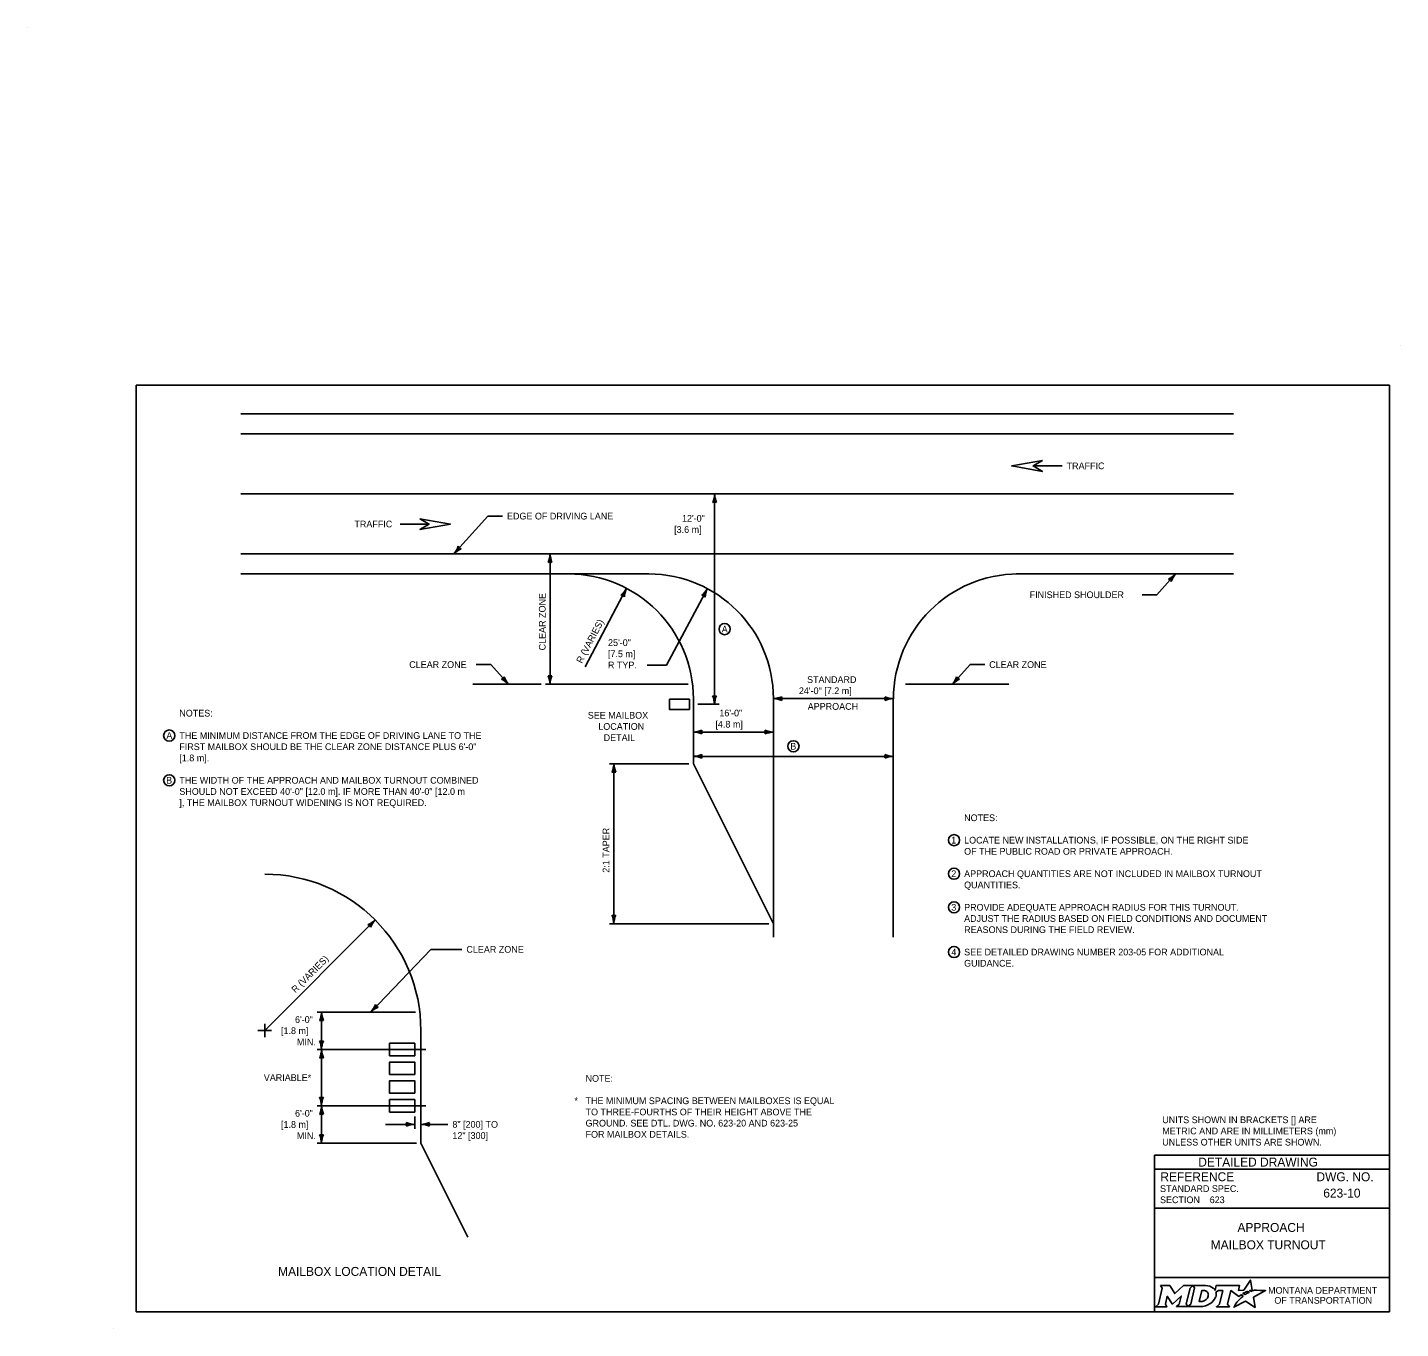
# Model space of a CAD drawing. Extents: x 49991.4 to 50021, y 49987.6 to 50011.4.
# Drawn here: x 50008.76 to 50021.04, y 49999.74 to 50011.36 of the extents above; entities that cross this region are included whole.
import ezdxf

# ---------------------------------------------------------------- set-up
doc = ezdxf.new("R2010")
doc.units = 0
for name, color, linetype in [('Default', 7, 'Continuous'), ('Level 1', 7, 'Continuous'), ('Level 2', 7, 'Continuous'), ('Level 3', 7, 'Continuous'), ('Level 4', 7, 'Continuous'), ('Level 5', 7, 'Continuous')]:
    doc.layers.add(name, color=color, linetype=linetype)

# ---------------------------------------------------------------- blocks, each defined once
blk = doc.blocks.new('ARR')
at = {"layer": 'Level 3'}
for centre, radius, start, end in [((1.5, 37), 37.1, 247.456, 267.6395), ((-21.4, 0), 9.13, 342.1388, 17.8612), ((1.9, -38.8), 38.8, 92.8273, 112.0772)]:
    blk.add_arc(centre, radius, start, end, dxfattribs=at)

msp = doc.modelspace()

# ---------------------------------------------------------------- linework, layer by layer
at = {"layer": 'Default'}
for points in [[(50018.893, 50000.121), (50018.907, 50000.097), (50018.874, 49999.954), (50018.848, 49999.931), (50018.95, 49999.931), (50018.936, 49999.954), (50018.952, 50000.024), (50018.996, 49999.955), (50019.002, 49999.955), (50019.077, 50000.025), (50019.06, 49999.954), (50019.035, 49999.932), (50019.137, 49999.932), (50019.123, 49999.955), (50019.156, 50000.097)], [(50019.156, 50000.097), (50019.182, 50000.121), (50019.099, 50000.121), (50019.02, 50000.048), (50018.975, 50000.12), (50018.893, 50000.121)], [(50019.295, 50000.121), (50019.182, 50000.121), (50019.196, 50000.098), (50019.163, 49999.954), (50019.137, 49999.932), (50019.248, 49999.932)], [(50019.7, 50000.068), (50019.69, 50000.074), (50019.702, 50000.076), (50019.713, 50000.078), (50019.696, 50000.168), (50019.636, 50000.077), (50019.589, 50000.076), (50019.599, 50000.12), (50019.39, 50000.121), (50019.38, 50000.078), (50019.374, 50000.086)], [(50019.319, 50000.034), (50019.318, 50000.026), (50019.315, 50000.017), (50019.311, 50000.008), (50019.305, 50000.001), (50019.299, 49999.994), (50019.291, 49999.988), (50019.282, 49999.983), (50019.273, 49999.979), (50019.264, 49999.977), (50019.255, 49999.976), (50019.239, 49999.976), (50019.263, 50000.076), (50019.279, 50000.076), (50019.286, 50000.075), (50019.294, 50000.073), (50019.301, 50000.07), (50019.307, 50000.066), (50019.311, 50000.061), (50019.315, 50000.055), (50019.318, 50000.049), (50019.319, 50000.042), (50019.32, 50000.038), (50019.319, 50000.034)], [(50019.387, 50000.062), (50019.411, 50000.075), (50019.448, 50000.075), (50019.42, 49999.954), (50019.392, 49999.931), (50019.508, 49999.931), (50019.491, 49999.954), (50019.52, 50000.075), (50019.591, 50000.023), (50019.612, 50000.038), (50019.632, 50000.027)], [(50019.576, 49999.971), (50019.561, 49999.947), (50019.556, 49999.939), (50019.55, 49999.931), (50019.548, 49999.926), (50019.653, 49999.979), (50019.737, 49999.924), (50019.724, 50000.017), (50019.831, 50000.075), (50019.782, 50000.076), (50019.751, 50000.077), (50019.731, 50000.077), (50019.724, 50000.075), (50019.719, 50000.074), (50019.711, 50000.072), (50019.7, 50000.068)], [(50019.59, 49999.987), (50019.59, 49999.987)], [(50019.65, 50000.04), (50019.648, 50000.039), (50019.629, 50000.048), (50019.639, 50000.054), (50019.644, 50000.056), (50019.652, 50000.06), (50019.658, 50000.063), (50019.666, 50000.066), (50019.673, 50000.068), (50019.685, 50000.061), (50019.681, 50000.059), (50019.676, 50000.056), (50019.672, 50000.054), (50019.667, 50000.051), (50019.665, 50000.05), (50019.662, 50000.049), (50019.66, 50000.047), (50019.658, 50000.046), (50019.655, 50000.044), (50019.652, 50000.042), (50019.65, 50000.04)], [(50019.293, 49999.939), (50019.302, 49999.942), (50019.315, 49999.947), (50019.335, 49999.958)]]:
    msp.add_lwpolyline(points, dxfattribs=at)
for centre, radius, start, end in [((50019.274, 50000.059), 0.118, 300.9103, 339.1383), ((50019.319, 50000.042), 0.0709, 339.5329, 15.8582)]:
    msp.add_arc(centre, radius, start, end, dxfattribs=at)
for centre, major_axis, ratio, start_param, end_param in [((50019.293, 50000.073), (0.0834, -0.0037), 0.568097, 0.61298, 1.570796), ((50019.349, 50000.081), (0.0361, -0.0295), 0.469099, 1.225588, 1.570796), ((50019.583, 49999.979), (-0.00694, -0.00806), 0.008222, 0, 3.137361), ((50019.6, 49999.997), (-0.0098, -0.0102), 0.016458, 3.141593, 6.279097), ((50019.621, 50000.017), (-0.0112, -0.0097), 0.021651, 3.157348, 6.283185), ((50019.248, 50000.08), (0, 0.148), 0.987302, 3.139398, 3.456847)]:
    msp.add_ellipse(centre, major_axis=major_axis, ratio=ratio, start_param=start_param, end_param=end_param, dxfattribs=at)
at = {"layer": 'Level 1'}
for p, q in [((50008.765, 50011.363), (50008.765, 50011.363)), ((50021.038, 50008.524), (50021.038, 50008.524)), ((50010.671, 50007.909), (50019.545, 50007.909)), ((50010.671, 50007.73), (50019.545, 50007.73)), ((50010.671, 50006.658), (50019.545, 50006.658)), ((50013.6, 50006.479), (50010.671, 50006.479)), ((50014.318, 50006.479), (50013.6, 50006.479)), ((50017.602, 50006.479), (50019.545, 50006.479)), ((50012.745, 50005.493), (50013.356, 50005.493)), ((50016.612, 50005.493), (50017.537, 50005.493)), ((50014.717, 50005.362), (50014.717, 50004.783)), ((50015.432, 50005.365), (50015.432, 50004.661)), ((50016.504, 50005.362), (50016.504, 50003.232)), ((50014.717, 50004.783), (50015.432, 50003.353)), ((50015.432, 50004.661), (50015.432, 50003.232)), ((50012.282, 50002.4), (50012.282, 50001.391)), ((50012.282, 50001.391), (50012.701, 50000.553)), ((50009.537, 49999.736), (50009.537, 49999.736))]:
    msp.add_line(p, q, dxfattribs=at)
for points in [[(50020.938, 50008.165), (50009.737, 50008.165), (50009.737, 49999.886), (50020.938, 49999.886)], [(50014.503, 50005.359), (50014.503, 50005.269), (50014.681, 50005.269), (50014.681, 50005.359)], [(50012.226, 50002.173), (50012.226, 50002.285), (50012.002, 50002.285), (50012.002, 50002.173)], [(50012.226, 50002.006), (50012.226, 50002.117), (50012.002, 50002.117), (50012.002, 50002.006)], [(50012.226, 50001.838), (50012.226, 50001.95), (50012.002, 50001.95), (50012.002, 50001.838)], [(50012.226, 50001.67), (50012.226, 50001.782), (50012.002, 50001.782), (50012.002, 50001.67)]]:
    msp.add_lwpolyline(points, close=True, dxfattribs=at)
for centre, radius, start, end in [((50013.6, 50005.362), 1.117, 0, 90), ((50014.318, 50005.365), 1.114, 360, 90), ((50017.622, 50005.362), 1.117, 90, 180), ((50010.885, 50002.4), 1.396, 0, 90)]:
    msp.add_arc(centre, radius, start, end, dxfattribs=at)
at = {"layer": 'Level 2'}
for centre in [(50014.996, 50005.986), (50010.032, 50005.035), (50015.611, 50004.939), (50010.032, 50004.635), (50017.047, 50004.1), (50017.047, 50003.8), (50017.047, 50003.5), (50017.047, 50003.1)]:
    msp.add_circle(centre, 0.05, dxfattribs=at)
at = {"layer": 'Level 3'}
for p, q in [((50018.013, 50007.445), (50017.753, 50007.445)), ((50014.906, 50006.658), (50014.906, 50007.194)), ((50012.577, 50006.658), (50012.88, 50006.996)), ((50012.88, 50006.996), (50013.011, 50006.996)), ((50012.095, 50006.925), (50012.355, 50006.925)), ((50013.436, 50006.658), (50013.436, 50005.493)), ((50014.906, 50005.314), (50014.906, 50006.658)), ((50018.858, 50006.293), (50019.026, 50006.479)), ((50013.751, 50005.649), (50014.12, 50006.351)), ((50014.478, 50005.665), (50014.843, 50006.348)), ((50018.727, 50006.293), (50018.858, 50006.293)), ((50012.775, 50005.669), (50012.907, 50005.669)), ((50012.907, 50005.669), (50013.065, 50005.493)), ((50014.303, 50005.665), (50014.478, 50005.665)), ((50017.19, 50005.669), (50017.032, 50005.493)), ((50017.321, 50005.669), (50017.19, 50005.669)), ((50014.669, 50005.493), (50013.396, 50005.493)), ((50014.757, 50005.314), (50014.946, 50005.314)), ((50015.432, 50005.365), (50016.504, 50005.365)), ((50014.717, 50005.066), (50015.432, 50005.066)), ((50014.677, 50004.783), (50013.966, 50004.783)), ((50014.006, 50004.783), (50014.006, 50003.353)), ((50014.717, 50004.849), (50016.504, 50004.849)), ((50010.885, 50002.4), (50011.873, 50003.387)), ((50015.392, 50003.353), (50013.966, 50003.353)), ((50012.369, 50003.124), (50011.834, 50002.564)), ((50012.648, 50003.124), (50012.369, 50003.124)), ((50012.232, 50002.564), (50011.353, 50002.564)), ((50011.393, 50002.229), (50011.393, 50002.564)), ((50010.885, 50002.46), (50010.885, 50002.4)), ((50010.885, 50002.4), (50010.825, 50002.4)), ((50010.885, 50002.4), (50010.885, 50002.34)), ((50010.945, 50002.4), (50010.885, 50002.4)), ((50011.393, 50002.229), (50011.393, 50001.726)), ((50011.393, 50001.726), (50011.393, 50001.391)), ((50012.226, 50001.63), (50012.226, 50001.52)), ((50012.226, 50001.56), (50011.964, 50001.56)), ((50012.523, 50001.56), (50012.282, 50001.56)), ((50012.242, 50001.391), (50011.353, 50001.391))]:
    msp.add_line(p, q, dxfattribs=at)
for points in [[(50017.836, 50007.493), (50017.563, 50007.445), (50017.836, 50007.396), (50017.753, 50007.445)], [(50012.272, 50006.973), (50012.545, 50006.925), (50012.272, 50006.877), (50012.355, 50006.925)]]:
    msp.add_lwpolyline(points, close=True, dxfattribs=at)
at = {"layer": 'Level 4'}
for p, q in [((50020.938, 50001.286), (50018.838, 50001.286)), ((50018.838, 50001.286), (50018.838, 49999.886)), ((50020.938, 50001.161), (50018.838, 50001.161)), ((50019.332, 50000.886), (50019.332, 50000.886)), ((50020.574, 50000.946), (50020.574, 50000.946)), ((50020.938, 50000.811), (50018.838, 50000.811)), ((50019.888, 50000.562), (50019.888, 50000.562)), ((50020.938, 50000.193), (50018.838, 50000.193))]:
    msp.add_line(p, q, dxfattribs=at)
at = {"layer": 'Level 5'}
for p, q in [((50010.671, 50007.194), (50019.545, 50007.194)), ((50012.326, 50002.229), (50011.353, 50002.229)), ((50012.326, 50001.726), (50011.353, 50001.726))]:
    msp.add_line(p, q, dxfattribs=at)

# ---------------------------------------------------------------- block references
at = {"layer": 'Level 3'}
for p, xscale, yscale, rotation in [((50014.906, 50007.194), 0.006, 0.006, 90), ((50012.577, 50006.658), 0.006000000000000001, 0.006, -131.9157369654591), ((50013.436, 50006.658), 0.006, 0.006, 90), ((50019.026, 50006.479), 0.006, 0.006000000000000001, 48.08426303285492), ((50014.12, 50006.351), 0.006000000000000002, 0.006, 62.28598908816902), ((50014.843, 50006.348), 0.006, 0.005999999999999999, 61.86112302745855), ((50013.065, 50005.493), 0.006, 0.006, -48.08426303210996), ((50013.436, 50005.493), 0.006, 0.006, -90), ((50017.032, 50005.493), 0.006, 0.006, -131.91573697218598), ((50014.906, 50005.314), 0.006, 0.006, -90), ((50015.432, 50005.365), 0.006, 0.006, 180), ((50014.717, 50005.066), 0.006, 0.006, 180), ((50014.006, 50004.783), 0.006, 0.006, 90), ((50014.717, 50004.849), 0.006, 0.006, 180), ((50014.006, 50003.353), 0.006, 0.006, -90), ((50011.873, 50003.387), 0.005999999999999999, 0.006, 44.99999999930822), ((50011.393, 50002.564), 0.006, 0.006, 90), ((50011.834, 50002.564), 0.006, 0.006, -133.71280017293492), ((50011.393, 50002.229), 0.006, 0.006, -90), ((50011.393, 50002.229), 0.006, 0.006, 90), ((50011.393, 50001.726), 0.006, 0.006, -90), ((50011.393, 50001.726), 0.006, 0.006, 90), ((50012.282, 50001.56), 0.006, 0.006, 180), ((50011.393, 50001.391), 0.006, 0.006, -90)]:
    msp.add_blockref('ARR', p, dxfattribs=dict(at, xscale=xscale, yscale=yscale, rotation=rotation))
at = {"layer": 'Level 3', "xscale": 0.006, "yscale": 0.006}
for p in [(50016.504, 50005.365), (50015.432, 50005.066), (50016.504, 50004.849), (50012.226, 50001.56)]:
    msp.add_blockref('ARR', p, dxfattribs=at)

# ---------------------------------------------------------------- texts
at = {"layer": 'Default'}
for s, p in [('MONTANA DEPARTMENT', (50019.854, 50000.047)), ('OF TRANSPORTATION', (50019.91, 49999.957))]:
    msp.add_text(s, height=0.06, dxfattribs=at).set_placement(p)
at = {"layer": 'Level 2'}
for s, height, p in [('TRAFFIC', 0.06, (50018.053, 50007.415)), ('EDGE OF DRIVING LANE', 0.06, (50013.051, 50006.966)), ('12\'-0"', 0.06, (50014.615, 50006.946)), ('TRAFFIC', 0.06, (50011.687, 50006.895)), ('[3.6 m]', 0.06, (50014.545, 50006.846)), ('CLEAR ZONE', 0.06, (50017.361, 50005.639)), ('STANDARD ', 0.06, (50015.733, 50005.505)), ('24\'-0" [7.2 m]', 0.06, (50015.66, 50005.405)), ('NOTES:', 0.06, (50010.122, 50005.205)), ('16\'-0"', 0.06, (50014.949, 50005.206)), ('APPROACH', 0.06, (50015.739, 50005.265)), ('SEE MAILBOX', 0.06, (50013.773, 50005.186)), ('LOCATION', 0.06, (50013.867, 50005.086)), ('[4.8 m]', 0.06, (50014.914, 50005.106)), ('THE MINIMUM DISTANCE FROM THE EDGE OF DRIVING LANE TO THE ', 0.06, (50010.122, 50005.005)), ('DETAIL', 0.06, (50013.915, 50004.986)), ('FIRST MAILBOX SHOULD BE THE CLEAR ZONE DISTANCE PLUS 6\'-0" ', 0.06, (50010.122, 50004.905)), ('[1.8 m].', 0.06, (50010.122, 50004.805)), ('THE WIDTH OF THE APPROACH AND MAILBOX TURNOUT COMBINED ', 0.06, (50010.122, 50004.605)), ('SHOULD NOT EXCEED 40\'-0" [12.0 m]. IF MORE THAN 40\'-0" [12.0 m', 0.06, (50010.122, 50004.505)), ('], THE MAILBOX TURNOUT WIDENING IS NOT REQUIRED. ', 0.06, (50010.122, 50004.405)), ('NOTES:', 0.06, (50017.137, 50004.27)), ('1', 0.06, (50017.021, 50004.07)), ('OF THE PUBLIC ROAD OR PRIVATE APPROACH.', 0.06, (50017.137, 50003.97)), ('LOCATE NEW INSTALLATIONS, IF POSSIBLE, ON THE RIGHT SIDE', 0.06, (50017.137, 50004.07)), ('2', 0.06, (50017.022, 50003.77)), ('APPROACH QUANTITIES ARE NOT INCLUDED IN MAILBOX TURNOUT', 0.06, (50017.137, 50003.77)), ('QUANTITIES.', 0.06, (50017.137, 50003.67)), ('3', 0.06, (50017.022, 50003.47)), ('PROVIDE ADEQUATE APPROACH RADIUS FOR THIS TURNOUT.  ', 0.06, (50017.137, 50003.47)), ('ADJUST THE RADIUS BASED ON FIELD CONDITIONS AND DOCUMENT', 0.06, (50017.137, 50003.37)), ('REASONS DURING THE FIELD REVIEW.', 0.06, (50017.137, 50003.27)), ('CLEAR ZONE', 0.06, (50012.688, 50003.094)), ('4', 0.06, (50017.023, 50003.07)), ('SEE DETAILED DRAWING NUMBER 203-05 FOR ADDITIONAL', 0.06, (50017.137, 50003.07)), ('GUIDANCE.', 0.06, (50017.137, 50002.97)), ('[1.8 m]', 0.06, (50011.031, 50002.367)), ('6\'-0"', 0.06, (50011.156, 50002.467)), ('MIN.', 0.06, (50011.173, 50002.267)), ('NOTE:', 0.06, (50013.753, 50001.941)), ('6\'-0"', 0.06, (50011.156, 50001.629)), ('*', 0.06, (50013.654, 50001.741)), ('THE MINIMUM SPACING BETWEEN MAILBOXES IS EQUAL', 0.06, (50013.753, 50001.741)), ('TO THREE-FOURTHS OF THEIR HEIGHT ABOVE THE', 0.06, (50013.753, 50001.641)), ('[1.8 m]', 0.06, (50011.031, 50001.529)), ('8" [200] TO', 0.06, (50012.563, 50001.53)), ('GROUND. SEE DTL. DWG. NO. 623-20 AND 623-25', 0.06, (50013.753, 50001.541)), ('UNITS SHOWN IN BRACKETS [] ARE ', 0.06, (50018.908, 50001.571)), ('MIN.', 0.06, (50011.173, 50001.429)), ('12" [300]', 0.06, (50012.563, 50001.43)), ('FOR MAILBOX DETAILS.', 0.06, (50013.753, 50001.441)), ('METRIC AND ARE IN MILLIMETERS (mm) ', 0.06, (50018.908, 50001.471)), ('UNLESS OTHER UNITS ARE SHOWN.', 0.06, (50018.908, 50001.371)), ('623-10', 0.08, (50020.347, 50000.906)), ('623', 0.06, (50019.332, 50000.856)), ('APPROACH', 0.08, (50019.58, 50000.599)), ('MAILBOX TURNOUT', 0.08, (50019.341, 50000.444)), ('MAILBOX LOCATION DETAIL', 0.08, (50011.005, 50000.206))]:
    msp.add_text(s, height=height, dxfattribs=at).set_placement(p)
for s, rotation, p in [('CLEAR ZONE', 90, (50013.396, 50005.796)), ('FINISHED SHOULDER', 360, (50017.723, 50006.263)), ('R (VARIES)', 62.286, (50013.72, 50005.675)), ('A', 360, (50014.97, 50005.956)), ('25\'-0"', 359.7046, (50013.954, 50005.836)), ('[7.5 m]', 359.7046, (50013.953, 50005.736)), ('CLEAR ZONE', 360, (50012.177, 50005.639)), ('R TYP.', 359.7046, (50013.953, 50005.636)), ('A', 360, (50010.006, 50005.005)), ('B', 360, (50015.583, 50004.909)), ('B', 360, (50010.004, 50004.605)), ('2:1 TAPER', 90, (50013.966, 50003.809)), ('R (VARIES)', 45, (50011.16, 50002.731)), ('VARIABLE*', 360, (50010.877, 50001.948))]:
    msp.add_text(s, height=0.06, rotation=rotation, dxfattribs=at).set_placement(p)
at = {"layer": 'Level 4'}
for s, height, p in [('DETAILED DRAWING', 0.0799, (50019.23, 50001.183)), ('REFERENCE', 0.08, (50018.891, 50001.052)), ('DWG. NO.', 0.08, (50020.286, 50001.052)), ('STANDARD SPEC.', 0.06, (50018.888, 50000.956)), ('SECTION', 0.06, (50018.888, 50000.856))]:
    msp.add_text(s, height=height, dxfattribs=at).set_placement(p)

doc.saveas('drawing.dxf')
